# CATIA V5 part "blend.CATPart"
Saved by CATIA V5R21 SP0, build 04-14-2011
Part number: Part1
Bounding box of the stored display mesh (mm): x -35 to 60.667, y -63.871 to 74.95, z -30 to 65.597
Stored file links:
  C:\Users\MoMo\Desktop\blend.CATPart
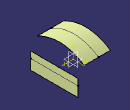
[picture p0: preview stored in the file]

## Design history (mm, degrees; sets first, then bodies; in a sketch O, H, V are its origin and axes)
Set1
  Extrude1: Element1 Sketch1, Lim1 -35, Lim2 -42
  Extrude2: Element1 Sketch2, Lim1 -19, Lim2 -30
Body1 (main body)
  Sketch1 on yz-plane, origin (0, 0, 0), H (0, 1, 0), V (0, 0, 1)
    spline S1 through (74.9496, 42.778) (0, 65.5972) (-63.8709, 47.7795)
    point P1 (0, 65.5972)
    coincidence: P1 V
  Sketch2 on xy-plane, origin (0, 0, 0), H (1, 0, 0), V (0, 1, 0)
    point P1 (60.6672, -63.8709)
    line L1 (60.6672, -63.8709) -> (60.6672, 74.9496)
    point P2 (60.6672, 74.9496)
    reference projected line E1 (-35, 74.9496) -> (42, 74.9496) from edge of Extrude1
    reference projected line E2 (42, -63.8709) -> (-35, -63.8709) from edge of Extrude1
    vertical: L1 V
    coincidence: P2 E1, P1 E2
